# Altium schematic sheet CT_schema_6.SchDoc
size 235 x 277 mm
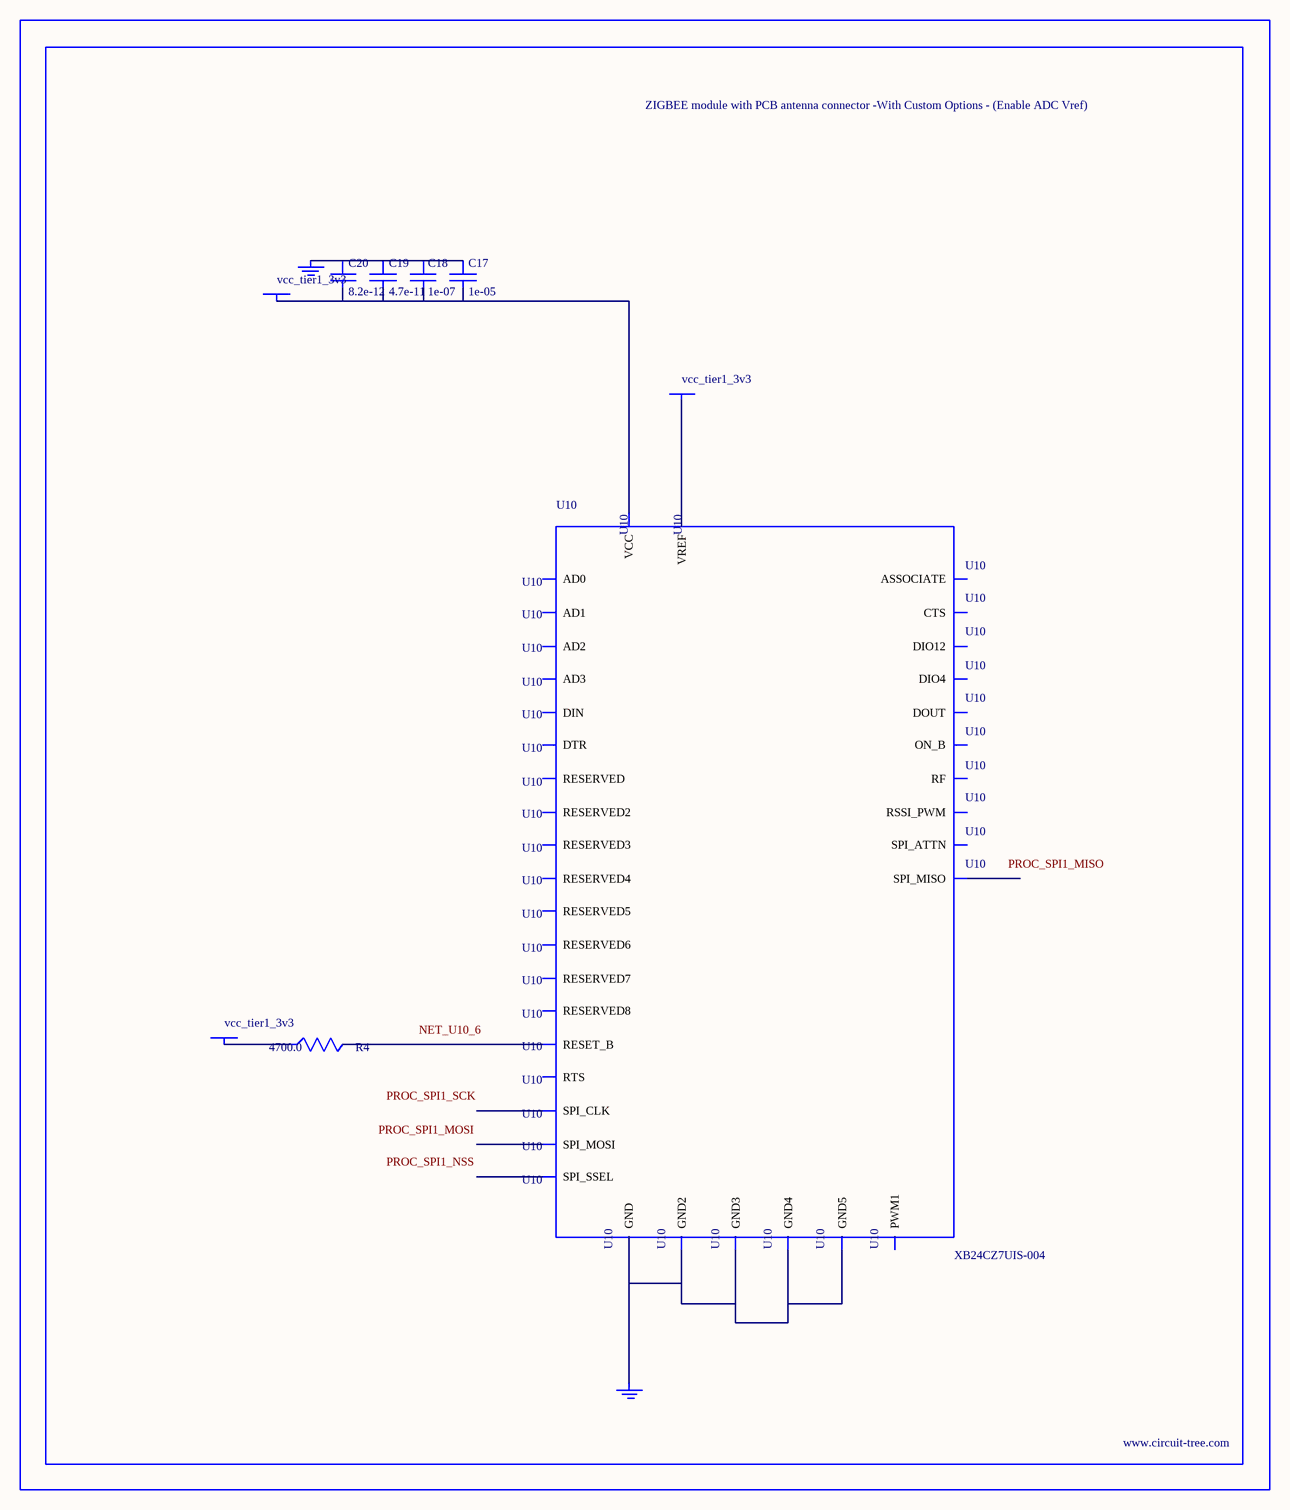
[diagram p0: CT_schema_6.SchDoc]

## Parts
BORDER5  (no value)
C17  1e-05  [C0805]
C18  1e-07  [C0402]
C19  4.7e-11  [C0402]
C20  8.2e-12  [C0603]
GND_INSTANCE_5_0  (no value)
GND_INSTANCE_5_1  (no value)
POWER_INSTANCE_5_0  vcc_tier1_3v3
POWER_INSTANCE_5_1  vcc_tier1_3v3
POWER_INSTANCE_5_2  vcc_tier1_3v3
R4  4700.0  [R0603]
U10  XB24CZ7UIS-004  [XB24CZ7UIS-004]

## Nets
NetC17_1: C17.1 C18.1 C19.1 C20.1 GND_INSTANCE_5_0.0(GND)
NetC17_2: C17.2 C18.2 C19.2 C20.2 POWER_INSTANCE_5_0.0(PWR) U10.2(VCC)
NetGND_INSTANCE_5_1_0: GND_INSTANCE_5_1.0(GND) U10.1(GND) U10.11(GND2) U10.13(GND3) U10.22(GND4) U10.35(GND5)
NetPOWER_INSTANCE_5_1_0: POWER_INSTANCE_5_1.0(PWR) R4.1
NetPOWER_INSTANCE_5_2_0: POWER_INSTANCE_5_2.0(PWR) U10.27(VREF)
NetR4_2: R4.2 U10.6(RESET_B)

Not connected (* = marked no-connect by the designer): U10 3(DOUT) 4(DIN) 5(DIO12) 7(RSSI_PWM) 8(PWM1) 9(RESERVED) 10(DTR) 12(SPI_ATTN) 14(SPI_CLK) 15(SPI_SSEL) 16(SPI_MOSI) 17(SPI_MISO) 18(RESERVED2) 19(RESERVED3) 20(RESERVED4) 21(RESERVED5) 23(RESERVED6) 24(DIO4) 25(CTS) 26(ON_B) 28(ASSOCIATE) 29(RTS) 30(AD3) 31(AD2) 32(AD1) 33(AD0) 34(RESERVED7) 36(RF) 37(RESERVED8)

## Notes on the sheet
- Labels drawn without touching a wire or pin: NET_U10_6, PROC_SPI1_MISO, PROC_SPI1_MOSI, PROC_SPI1_NSS, PROC_SPI1_SCK

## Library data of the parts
BORDER5 = BORDER_PAGE5
C17 = C0805C106K8RACTU
C18 = C0402C104K3RACTU
C19 = C0402C470K3RAC
C20 = 06035J8R2BBTTR
GND_INSTANCE_5_0 GND_INSTANCE_5_1 = GND
POWER_INSTANCE_5_0-POWER_INSTANCE_5_2 = PWR
R4 = RC0603JR-074K7L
